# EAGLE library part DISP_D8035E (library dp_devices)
VFD 7-Segment Display Mfr no: NEC LD8035E D-8035-E PDF
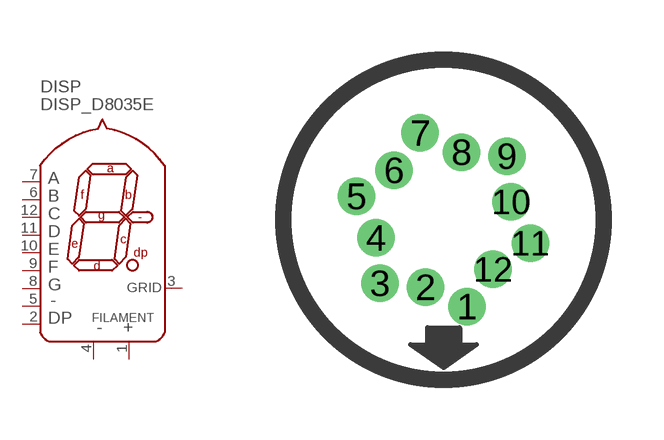
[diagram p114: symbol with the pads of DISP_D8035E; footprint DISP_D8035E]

Designator prefix DISP

## DISP_D8035E  [DISP_D8035E]
1  F+  pwr
2  DP  in
3  GRID  in
4  F-  pwr
5  -  in
6  B  in
7  A  in
8  G  in
9  F  in
10  E  in
11  D  in
12  C  in

## Footprint DISP_D8035E (pad centres in mm)
drill 0.43 round: 1 0.582,-2.173; 2 -0.453,-1.69; 3 -1.591,-1.591; 4 -1.69,-0.453; 5 -2.173,0.582; 6 -1.237,1.237; 7 -0.582,2.173; 8 0.453,1.69; 9 1.591,1.591; 10 1.69,0.453; 11 2.173,-0.582; 12 1.237,-1.237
